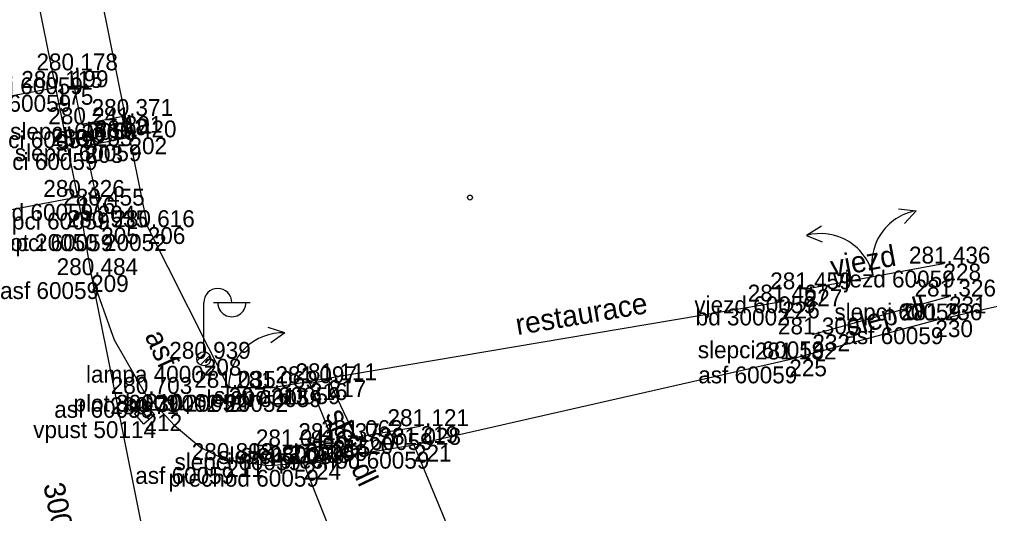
# Model space of a CAD drawing. Extents: x -728659 to -728362, y -1073110 to -1072943.
# Drawn here: x -728508.67 to -728474.14, y -1073021.92 to -1073004.33 of the extents above; entities that cross this region are included whole.
import ezdxf

# ---------------------------------------------------------------- set-up
doc = ezdxf.new("R2010")
doc.units = 0
for name, color, linetype in [('Vrstva 17', 7, 'Continuous'), ('Vrstva 23', 7, 'Continuous'), ('Vrstva 25', 7, 'Continuous'), ('Vrstva 43', 7, 'Continuous'), ('Vrstva 51', 7, 'Continuous'), ('Vrstva 55', 7, 'Continuous'), ('Vrstva 57', 7, 'Continuous'), ('Vrstva 59', 7, 'Continuous'), ('Vrstva 60', 7, 'Continuous'), ('Vrstva 61', 7, 'Continuous'), ('Vrstva 62', 7, 'Continuous')]:
    doc.layers.add(name, color=color, linetype=linetype)

msp = doc.modelspace()

# ---------------------------------------------------------------- linework, layer by layer
at = {"layer": 'Vrstva 17'}
msp.add_line((-728504.103, -1073011.723), (-728508.888, -1072988.018), dxfattribs=at)
msp.add_lwpolyline([(-728499.729, -1073017.446), (-728501.22, -1073017.439), (-728504.103, -1073011.723)], dxfattribs=at)
at = {"layer": 'Vrstva 23'}
for p, q in [((-728499.729, -1073017.446), (-728481.523, -1073014.371)), ((-728499.22, -1073015.489), (-728499.82, -1073015.289)), ((-728499.22, -1073015.489), (-728499.72, -1073015.839))]:
    msp.add_line(p, q, dxfattribs=at)
for points in [[(-728477.387, -1073011.078), (-728476.758, -1073011.142), (-728477.169, -1073011.593)], [(-728480.119, -1073011.693), (-728480.66, -1073012.02), (-728480.096, -1073012.252)]]:
    msp.add_lwpolyline(points, dxfattribs=at)
for centre, start, end in [((-728476.418, -1073013.028), 100.205, 193.7249), ((-728480.158, -1073013.871), 11.6555, 105.1754), ((-728499.303, -1073017.404), 87.5148, 181.0347)]:
    msp.add_arc(centre, 1.917, start, end, dxfattribs=at)
at = {"layer": 'Vrstva 25'}
for p, q in [((-728502.11, -1073016.157), (-728502.11, -1073014.407)), ((-728501.76, -1073014.407), (-728500.46, -1073014.407)), ((-728502.349, -1073016.48), (-728502.038, -1073016.169)), ((-728502.23, -1073016.625), (-728501.891, -1073016.287))]:
    msp.add_line(p, q, dxfattribs=at)
msp.add_circle((-728502.11, -1073016.407), 0.25, dxfattribs=at)
for centre, start, end in [((-728501.61, -1073014.407), 0, 180), ((-728501.11, -1073014.413), 179.2974, 0.7026)]:
    msp.add_arc(centre, 0.5, start, end, dxfattribs=at)
at = {"layer": 'Vrstva 43'}
msp.add_lwpolyline([(-728504.38, -1073018.188), (-728504.19, -1073018.026), (-728503.866, -1073018.406), (-728504.246, -1073018.73), (-728504.57, -1073018.35), (-728504.38, -1073018.188), (-728504.056, -1073018.568)], dxfattribs=at)
at = {"layer": 'Vrstva 51'}
for p, q in [((-728478.281, -1073013.483), (-728475.783, -1073013.02)), ((-728480.722, -1073013.936), (-728478.281, -1073013.483)), ((-728480.448, -1073015.539), (-728475.586, -1073014.192))]:
    msp.add_line(p, q, dxfattribs=at)
for points in [[(-728507.377, -1073006.769), (-728510.163, -1072993.092), (-728513.027, -1072976.664), (-728515.483, -1072964.348)], [(-728506.838, -1073006.146), (-728506.465, -1073008.064), (-728504.923, -1073007.768), (-728504.755, -1073008.53), (-728506.32, -1073008.839), (-728505.884, -1073010.959), (-728505.76, -1073011.731)], [(-728507.377, -1073006.769), (-728515.484, -1073008.258), (-728514.696, -1073012.189), (-728506.595, -1073010.648), (-728507.377, -1073006.769)], [(-728494.628, -1073019.466), (-728481.269, -1073016.431), (-728476.07, -1073015.036), (-728454.183, -1073010.103)], [(-728506.595, -1073010.648), (-728506.12, -1073013.431), (-728505.297, -1073015.728), (-728504.193, -1073017.656), (-728503.154, -1073018.784), (-728502.216, -1073019.565), (-728501.31, -1073020.009), (-728499.799, -1073020.206), (-728498.56, -1073020.107)], [(-728499.075, -1073019.523), (-728497.518, -1073019.3), (-728498.332, -1073017.276), (-728497.666, -1073017.17), (-728496.705, -1073019.192), (-728494.391, -1073018.803)], [(-728498.56, -1073020.107), (-728494.628, -1073019.466), (-728491.401, -1073027.273), (-728495.275, -1073028.394), (-728498.56, -1073020.107)]]:
    msp.add_lwpolyline(points, dxfattribs=at)
at = {"layer": 'Vrstva 55'}
msp.add_line((-728501.19, -1073037.94), (-728506.11, -1073013.42), dxfattribs=at)
at = {"layer": 'Vrstva 59'}
msp.add_circle((-728492.635, -1073010.673), 0.0873, dxfattribs=at)
at = {"layer": 'Vrstva 60'}
for p, q in [((-728506.838, -1073006.146), (-728506.838, -1073006.146)), ((-728507.377, -1073006.769), (-728507.377, -1073006.769)), ((-728504.923, -1073007.768), (-728504.923, -1073007.768)), ((-728506.465, -1073008.064), (-728506.465, -1073008.064)), ((-728504.755, -1073008.53), (-728504.755, -1073008.53)), ((-728506.32, -1073008.839), (-728506.32, -1073008.839)), ((-728506.595, -1073010.648), (-728506.595, -1073010.648)), ((-728505.884, -1073010.959), (-728505.884, -1073010.959)), ((-728505.76, -1073011.731), (-728505.76, -1073011.731)), ((-728504.103, -1073011.723), (-728504.103, -1073011.723)), ((-728475.783, -1073013.02), (-728475.783, -1073013.02)), ((-728506.12, -1073013.431), (-728506.12, -1073013.431)), ((-728480.722, -1073013.936), (-728480.722, -1073013.936)), ((-728481.523, -1073014.371), (-728481.523, -1073014.371)), ((-728475.586, -1073014.192), (-728475.586, -1073014.192)), ((-728476.07, -1073015.036), (-728476.07, -1073015.036)), ((-728480.448, -1073015.539), (-728480.448, -1073015.539)), ((-728502.11, -1073016.407), (-728502.11, -1073016.407)), ((-728481.269, -1073016.431), (-728481.269, -1073016.431)), ((-728497.666, -1073017.17), (-728497.666, -1073017.17)), ((-728501.22, -1073017.439), (-728501.22, -1073017.439)), ((-728499.729, -1073017.446), (-728499.729, -1073017.446)), ((-728498.332, -1073017.276), (-728498.332, -1073017.276)), ((-728504.193, -1073017.656), (-728504.193, -1073017.656)), ((-728504.218, -1073018.378), (-728504.218, -1073018.378)), ((-728494.391, -1073018.803), (-728494.391, -1073018.803)), ((-728496.705, -1073019.192), (-728496.705, -1073019.192)), ((-728499.075, -1073019.523), (-728499.075, -1073019.523)), ((-728497.518, -1073019.3), (-728497.518, -1073019.3)), ((-728494.628, -1073019.466), (-728494.628, -1073019.466)), ((-728501.31, -1073020.009), (-728501.31, -1073020.009)), ((-728498.56, -1073020.107), (-728498.56, -1073020.107))]:
    msp.add_line(p, q, dxfattribs=at)

# ---------------------------------------------------------------- texts
at = {"layer": 'Vrstva 23'}
msp.add_text('restaurace', height=0.75, rotation=9.5868, dxfattribs=at).set_placement((-728490.945, -1073015.568))
at = {"layer": 'Vrstva 51'}
for s, rotation, p in [('slep dla', 10.8662, (-728507.365, -1073009.034)), ('vjezd', 10.5068, (-728479.728, -1073013.51)), ('slep dl', 15.4852, (-728479.123, -1073015.635)), ('asf', 294.5175, (-728504.225, -1073015.592)), ('slep dl', 295.4204, (-728497.794, -1073018.396))]:
    msp.add_text(s, height=0.75, rotation=rotation, dxfattribs=at).set_placement(p)
at = {"layer": 'Vrstva 57'}
msp.add_text('3005/9', height=0.75, rotation=280.9963, dxfattribs=at).set_placement((-728507.822, -1073020.889))
at = {"layer": 'Vrstva 60'}
for s, p in [('199', (-728506.838, -1073006.746)), ('175', (-728507.377, -1073007.369)), ('201', (-728504.923, -1073008.368)), ('200', (-728506.465, -1073008.664)), ('202', (-728504.755, -1073009.13)), ('203', (-728506.32, -1073009.439)), ('176', (-728506.595, -1073011.248)), ('204', (-728505.884, -1073011.559)), ('205', (-728505.76, -1073012.331)), ('206', (-728504.103, -1073012.323)), ('228', (-728475.783, -1073013.62)), ('209', (-728506.12, -1073014.031)), ('227', (-728480.722, -1073014.536)), ('226', (-728481.523, -1073014.971)), ('231', (-728475.586, -1073014.792)), ('230', (-728476.07, -1073015.636)), ('232', (-728480.448, -1073016.139)), ('208', (-728502.11, -1073017.007)), ('225', (-728481.269, -1073017.031)), ('217', (-728497.666, -1073017.77)), ('207', (-728501.22, -1073018.039)), ('213', (-728499.729, -1073018.046)), ('216', (-728498.332, -1073017.876)), ('210', (-728504.193, -1073018.256)), ('212', (-728504.218, -1073018.978)), ('219', (-728494.391, -1073019.403)), ('220', (-728496.705, -1073019.792)), ('214', (-728499.075, -1073020.123)), ('215', (-728497.518, -1073019.9)), ('221', (-728494.628, -1073020.066)), ('211', (-728501.31, -1073020.609)), ('224', (-728498.56, -1073020.707))]:
    msp.add_text(s, height=0.6, dxfattribs=at).set_placement(p)
at = {"layer": 'Vrstva 61'}
for s, p in [('280.178', (-728508.065, -1073006.146)), ('280.115', (-728508.605, -1073006.769)), ('280.371', (-728506.102, -1073007.768)), ('280.241', (-728507.644, -1073008.064)), ('280.420', (-728505.98, -1073008.53)), ('280.283', (-728507.546, -1073008.839)), ('280.326', (-728507.821, -1073010.648)), ('280.455', (-728507.112, -1073010.959)), ('280.535', (-728506.988, -1073011.731)), ('280.616', (-728505.329, -1073011.723)), ('281.436', (-728477.009, -1073013.02)), ('280.484', (-728507.345, -1073013.431)), ('281.459', (-728481.949, -1073013.936)), ('281.326', (-728476.812, -1073014.192)), ('281.467', (-728482.749, -1073014.371)), ('281.236', (-728477.296, -1073015.036)), ('281.300', (-728481.673, -1073015.539)), ('280.939', (-728503.337, -1073016.407)), ('281.182', (-728482.493, -1073016.431)), ('281.035', (-728502.448, -1073017.439)), ('281.097', (-728499.558, -1073017.276)), ('281.111', (-728498.845, -1073017.17)), ('280.703', (-728505.419, -1073017.656)), ('281.069', (-728500.956, -1073017.446)), ('280.714', (-728505.443, -1073018.378)), ('281.121', (-728495.57, -1073018.803)), ('281.037', (-728498.744, -1073019.3)), ('281.062', (-728497.929, -1073019.192)), ('281.028', (-728495.855, -1073019.466)), ('281.041', (-728500.254, -1073019.523)), ('280.898', (-728502.537, -1073020.009)), ('280.968', (-728499.787, -1073020.107))]:
    msp.add_text(s, height=0.6, dxfattribs=at).set_placement(p)
at = {"layer": 'Vrstva 62'}
for s, p in [('slepci 60059', (-728510.916, -1073006.996)), ('prechod 60059', (-728512.182, -1073007.619)), ('slepci 60059', (-728509.001, -1073008.618)), ('slepci 60059', (-728510.543, -1073008.914)), ('slepci 60059', (-728508.833, -1073009.38)), ('slepci 60059', (-728510.398, -1073009.689)), ('prechod 60059', (-728511.4, -1073011.498)), ('slepci 60059', (-728509.962, -1073011.809)), ('slepci 60059', (-728509.838, -1073012.581)), ('plot 20050 20052', (-728509.63, -1073012.573)), ('vjezd 60059', (-728479.709, -1073013.87)), ('asf 60059', (-728509.359, -1073014.281)), ('vjezd 60059', (-728484.648, -1073014.786)), ('slepci 60059', (-728479.664, -1073015.042)), ('bd 30002', (-728484.603, -1073015.221)), ('asf 60059', (-728479.309, -1073015.886)), ('slepci 60059', (-728484.526, -1073016.389)), ('lampa 40007', (-728506.301, -1073017.257)), ('asf 60059', (-728484.508, -1073017.281)), ('slepci 60059', (-728502.41, -1073018.126)), ('slepci 60059', (-728501.744, -1073018.02)), ('plot 30009 20052', (-728506.747, -1073018.289)), ('bd 30002 20052', (-728504.912, -1073018.296)), ('asf 60059', (-728507.432, -1073018.506)), ('vpust 50114', (-728508.18, -1073019.228)), ('slepci 60059', (-728498.469, -1073019.653)), ('slepci 60059', (-728501.596, -1073020.15)), ('slepci 60059', (-728500.783, -1073020.042)), ('slepci 60059', (-728503.153, -1073020.373)), ('prechod 60059', (-728499.433, -1073020.316)), ('asf 60059', (-728504.549, -1073020.859)), ('prechod 60059', (-728503.365, -1073020.957))]:
    msp.add_text(s, height=0.6, dxfattribs=at).set_placement(p)

doc.saveas('drawing.dxf')
